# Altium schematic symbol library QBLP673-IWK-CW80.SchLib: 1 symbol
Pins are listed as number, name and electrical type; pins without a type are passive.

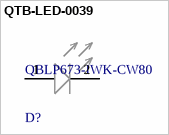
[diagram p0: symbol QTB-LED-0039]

## QTB-LED-0039
designator D?, comment QBLP673-IWK-CW80
LED COOL WHITE 2PLCC SMD; Manufacturer: QT Brightek (QTB); Lens Size: 1.7mm; Luminous Intensity: 5100mcd; Lens Transparency: Diffused; Test Current: 60mA; Lens Color: Yellow; Lens Style: Oval with Flat Top; Forward Voltage: 2.9V; Viewing Angle: 120°
footprint QBLP673-IWK-CW80
pins: 1 ANODE (+), 2 CATHODE (-)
